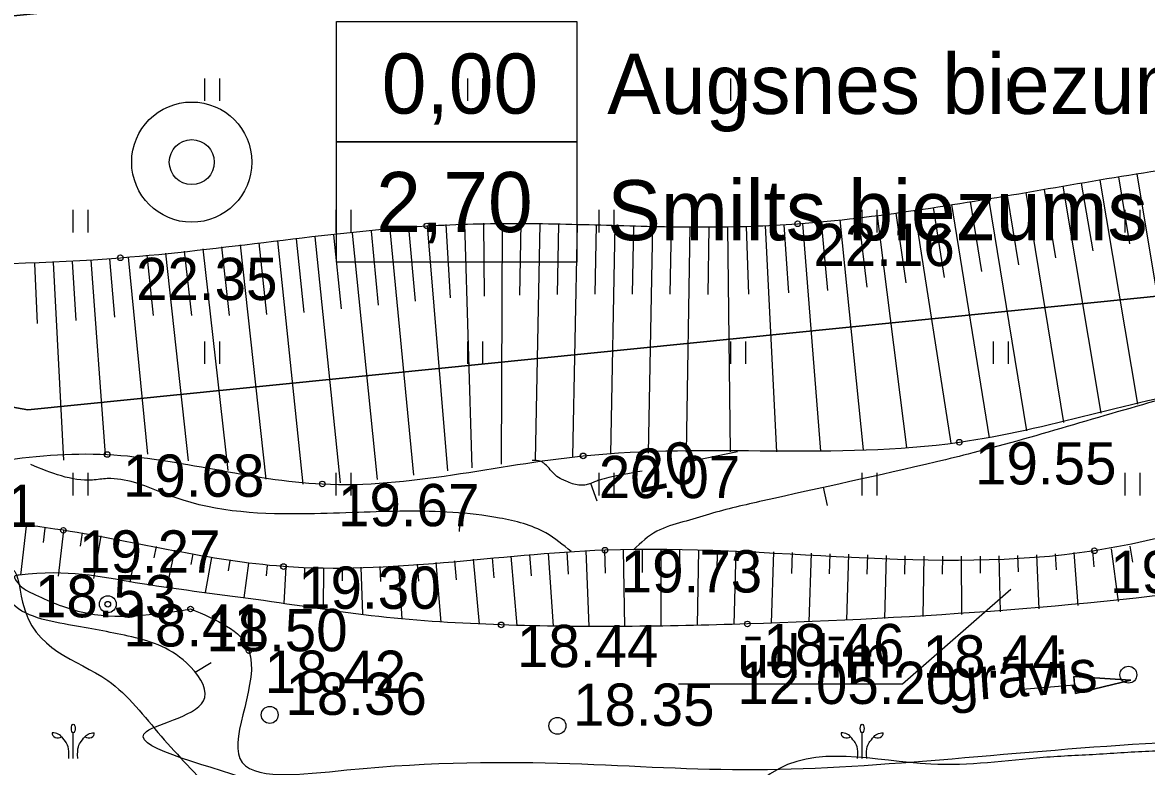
# Model space of a CAD drawing. Extents: x 521824 to 524158, y 294774 to 296228.
# Drawn here: x 522086.65 to 522116.57, y 296008.78 to 296028.59 of the extents above; entities that cross this region are included whole.
import ezdxf

# ---------------------------------------------------------------- set-up
doc = ezdxf.new("R2010")
doc.units = 0
for name, color, linetype in [('GL Urbumi Krajumu aprekina plans', 7, 'Continuous'), ('GL4 Segkartas izplatības laukums', 7, 'Continuous'), ('GL7 Citi Izplatības laukumi', 7, 'Continuous'), ('HIDG_AATZ_####_TKST_#', 7, 'Continuous'), ('HIDG_ELEM_####_####_#', 7, 'Continuous'), ('HIDG_GRAV_####_####_#', 7, 'Continuous'), ('HIDG_GRAV_####_TKST_#', 7, 'Continuous'), ('HIDG_UATZ_####_TKST_#', 7, 'Continuous'), ('RELJ_AATZ_####_TKST_#', 7, 'Continuous'), ('RELJ_ELEM_####_####_#', 7, 'Continuous'), ('RELJ_HORZ_####_TKST_#', 7, 'Continuous'), ('RELJ_HORZ_PAMT_####_#', 7, 'Continuous'), ('RELJ_HORZ_RESN_####_#', 7, 'Continuous'), ('RELJ_NOGA_####_####_#', 7, 'Continuous'), ('RELJ_NOGL_####_####_#', 7, 'Continuous'), ('TERT_ELEM_####_####_#', 7, 'Continuous'), ('TERT_KONT_####_####_#', 7, 'Continuous')]:
    doc.layers.add(name, color=color, linetype=linetype)

msp = doc.modelspace()

# ---------------------------------------------------------------- linework, layer by layer
at = {"layer": 'GL Urbumi Krajumu aprekina plans'}
for points in [[(522095.004, 296028.61), (522101.404, 296028.61), (522101.404, 296025.41), (522095.004, 296025.41)], [(522095.004, 296025.41), (522101.404, 296025.41), (522101.404, 296022.21), (522095.004, 296022.21)]]:
    msp.add_lwpolyline(points, close=True, dxfattribs=at)
for radius in [1.6, 0.6]:
    msp.add_circle((522091.154, 296024.871), radius, dxfattribs=at)
at = {"layer": 'GL4 Segkartas izplatības laukums'}
msp.add_lwpolyline([(522035.409, 296019.72), (522041.36, 296024.307), (522231.747, 296043.148), (522236.101, 296038.183), (522198.651, 296029.427), (522189.713, 296025.592), (522167.466, 296021.53), (522139.559, 296023.596), (522113.856, 296021.004), (522086.791, 296018.275), (522076.123, 296020.164), (522036.859, 296015.29)], close=True, dxfattribs=at)
at = {"layer": 'GL7 Citi Izplatības laukumi'}
msp.add_lwpolyline([(522036.859, 296015.29), (522076.123, 296020.164), (522086.791, 296018.275), (522113.856, 296021.004), (522139.559, 296023.596), (522167.466, 296021.53), (522189.713, 296025.592), (522198.651, 296029.427), (522236.101, 296038.183), (522231.747, 296043.148), (522041.36, 296024.307), (522035.409, 296019.72), (522036.859, 296015.29)], dxfattribs=at)
at = {"layer": 'HIDG_ELEM_####_####_#'}
for p, q in [((522114.675, 296010.731), (522114.637, 296011.18)), ((522114.637, 296011.18), (522116.151, 296011.082)), ((522116.151, 296011.082), (522114.675, 296010.731)), ((522113.161, 296010.829), (522114.656, 296010.956))]:
    msp.add_line(p, q, dxfattribs=at)
msp.add_lwpolyline([(522114.656, 296010.956), (522114.675, 296010.731), (522116.151, 296011.082), (522114.637, 296011.18), (522114.656, 296010.956)], dxfattribs=at)
for centre in [(522088.919, 296013.103), (522116.087, 296011.227), (522093.229, 296010.157), (522100.887, 296009.867)]:
    msp.add_circle(centre, 0.225, dxfattribs=at)
at = {"layer": 'HIDG_GRAV_####_####_#'}
for points in [[(522091.121, 296012.976), (522092.677, 296011.868), (522092.434, 296009), (522095.282, 296008.691), (522106.173, 296008.702), (522116.886, 296009.415), (522127.197, 296009.97), (522145.108, 296014.247), (522158.761, 296014.777), (522175.265, 296015.722), (522181.257, 296017.136), (522181.909, 296017.173), (522183.274, 296011.283)], [(522135.118, 296016.825), (522133.045, 296016.353), (522119.718, 296013.704), (522105.945, 296012.578), (522099.392, 296012.553), (522096.134, 296012.774), (522092.859, 296013.228), (522089.643, 296013.676), (522086.561, 296013.88), (522086.436, 296013.837), (522086.479, 296013.725), (522086.923, 296013.385), (522088.207, 296012.901), (522091.121, 296012.976)]]:
    msp.add_spline(points, degree=3, dxfattribs=at)
at = {"layer": 'HIDG_UATZ_####_TKST_#'}
msp.add_lwpolyline([(522104.107, 296010.988), (522110.073, 296010.988), (522112.956, 296013.503)], dxfattribs=at)
at = {"layer": 'RELJ_ELEM_####_####_#'}
for centre in [(522107.283, 296023.23), (522097.412, 296023.172), (522089.253, 296022.325), (522111.587, 296017.416), (522088.904, 296017.088), (522101.572, 296017.052), (522094.629, 296016.304), (522087.735, 296015.07), (522102.155, 296014.541), (522115.182, 296014.525), (522093.594, 296014.106), (522088.919, 296013.103), (522091.121, 296012.976), (522099.392, 296012.553), (522105.945, 296012.578), (522092.677, 296011.868)]:
    msp.add_circle(centre, 0.075, dxfattribs=at)
at = {"layer": 'RELJ_HORZ_PAMT_####_#'}
for p, q in [((522108.079, 296015.73), (522107.97, 296016.218)), ((522098.278, 296015.041), (522098.309, 296015.54)), ((522091.671, 296011.545), (522091.242, 296011.288))]:
    msp.add_line(p, q, dxfattribs=at)
for points in [[(522117.582, 296018.72), (522117.297, 296018.644), (522111.943, 296017.13), (522110.977, 296016.893), (522106.356, 296015.854), (522104.932, 296015.502), (522104.229, 296015.292), (522103.534, 296015.045), (522102.914, 296014.555)], [(522101.255, 296014.503), (522100.578, 296015), (522099.347, 296015.396), (522098.1, 296015.548), (522095.59, 296015.547), (522094.254, 296015.508), (522090.709, 296015.941), (522089.262, 296016.424), (522088.906, 296016.446), (522088.511, 296016.409), (522086.87, 296016.818)], [(522148.922, 295987.907), (522148.552, 295987.672), (522148.13, 295987.547), (522142.145, 295984.715), (522140.627, 295984.14), (522138.684, 295984.539), (522138.079, 295984.82), (522136.131, 295985.03), (522135.49, 295984.543), (522137.464, 295983.3), (522138.906, 295981.587), (522137.92, 295981.159), (522136.668, 295979.841), (522134.454, 295979.765), (522132.917, 295981.68), (522132.347, 295981.94), (522130.67, 295983.065), (522129.163, 295984.385), (522127.535, 295986.166), (522125.611, 295988.145), (522124.556, 295989.313), (522123.674, 295991.099), (522122.931, 295991.88), (522120.148, 295992.607), (522113.348, 295989.576), (522112.896, 295989.445), (522112.055, 295989.829), (522111.032, 295990.862), (522110.41, 295992.733), (522110.011, 295994.047), (522109.634, 295994.629), (522107.294, 295996.519), (522107.125, 295997.948), (522109.054, 295999.781), (522111.627, 295999.833), (522112.509, 295999.607), (522113.225, 295999.56), (522116.018, 295998.918), (522117.525, 295998.295), (522117.804, 295999.078), (522117.857, 296000.377), (522117.21, 296003.104), (522115.45, 296003.973), (522113.854, 296004.668), (522112.181, 296005.288), (522110.957, 296005.073), (522109.538, 296004.776), (522107.962, 296005.969), (522108.089, 296007.122), (522109.448, 296007.712), (522113.238, 296007.845), (522113.411, 296007.152), (522113.904, 296006.876), (522116.143, 296006.873), (522119.594, 296006.195), (522119.864, 296006.152), (522119.969, 296006.174), (522125.143, 296008.842), (522127.842, 296009.01), (522129.451, 296008.699), (522130.726, 296008.377), (522130.898, 296008.393), (522131.43, 296008.639), (522134.341, 296010.531), (522136.866, 296011.095), (522140.038, 296011.621), (522143.287, 296012.722), (522147.223, 296013.232), (522147.912, 296013.352), (522151.159, 296013.727), (522152.637, 296013.188), (522160.473, 296010.584), (522163.167, 296012.474), (522166.885, 296013.245), (522174.018, 296014.184), (522179.448, 296015.31), (522180.074, 296015.597), (522181.317, 296015.467), (522181.799, 296014.868), (522182.175, 296012.697), (522181.883, 296011.954), (522177.242, 296010.373), (522176.264, 296009.891), (522175.768, 296009.558), (522172.684, 296008.401), (522168.721, 296007.952), (522167.696, 296007.902), (522160.834, 296005.775), (522159.869, 296005.009), (522158.414, 295999.127), (522158.015, 295997.98), (522157.507, 295997.03)], [(522147.001, 296013.879), (522145.334, 296014.111), (522144.908, 296014.079), (522138.003, 296012.088), (522137.814, 296012.008), (522135.146, 296011.271), (522131.635, 296010.287), (522130.341, 296009.639), (522127.864, 296009.75), (522127.714, 296009.761), (522127.564, 296009.8), (522127.264, 296009.832), (522127.105, 296009.79), (522126.615, 296009.677), (522125.425, 296009.552), (522124.235, 296009.457), (522121.853, 296009.334), (522117.084, 296009.201), (522116.821, 296009.194), (522115.322, 296009.109), (522113.823, 296009.021), (522110.825, 296008.845), (522106.552, 296008.587), (522106.42, 296008.498), (522105.24, 296008.381), (522103.71, 296008.042), (522102.575, 296008.01), (522101.436, 296008.101), (522100.295, 296008.227), (522099.156, 296008.295), (522097.506, 296008.302), (522096.685, 296008.185), (522096.274, 296008.062), (522096.069, 296007.981), (522095.864, 296007.884), (522092.757, 296008.408), (522089.948, 296009.718), (522091.502, 296010.619), (522091.012, 296011.544), (522089.457, 296012.256), (522087.875, 296012.556), (522086.266, 296013.266), (522086.078, 296014.194)]]:
    msp.add_spline(points, degree=3, dxfattribs=at)
at = {"layer": 'RELJ_HORZ_RESN_####_#'}
for p, q in [((522105.685, 296017.157), (522104.348, 296016.884)), ((522101.946, 296015.85), (522101.775, 296016.32))]:
    msp.add_line(p, q, dxfattribs=at)
msp.add_spline([(522103.148, 296016.646), (522102.129, 296016.442), (522101.999, 296016.405), (522101.872, 296016.357), (522101.745, 296016.309), (522101.682, 296016.289), (522101.618, 296016.275), (522101.454, 296016.272), (522101.288, 296016.311), (522101.122, 296016.376), (522101.039, 296016.414), (522100.957, 296016.452), (522100.798, 296016.57), (522100.664, 296016.722), (522100.529, 296016.856), (522100.451, 296016.901), (522100.363, 296016.922), (522100.219, 296016.932)], degree=3, dxfattribs=at)
at = {"layer": 'RELJ_NOGA_####_####_#'}
for p, q in [((522115.82, 296024.477), (522116.118, 296022.698)), ((522116.313, 296024.56), (522117.29, 296018.655)), ((522114.341, 296024.229), (522115.353, 296018.186)), ((522114.834, 296024.312), (522115.137, 296022.511)), ((522115.327, 296024.395), (522116.332, 296018.429)), ((522112.367, 296023.903), (522113.371, 296017.721)), ((522112.861, 296023.984), (522113.163, 296022.138)), ((522113.354, 296024.065), (522114.358, 296017.943)), ((522113.847, 296024.146), (522114.15, 296022.321)), ((522110.392, 296023.586), (522111.359, 296017.389)), ((522110.886, 296023.665), (522111.184, 296021.802)), ((522111.38, 296023.744), (522112.38, 296017.533)), ((522111.874, 296023.823), (522112.176, 296021.963)), ((522107.911, 296023.283), (522108.077, 296021.456)), ((522108.409, 296023.331), (522109.027, 296017.213)), ((522108.906, 296023.384), (522109.122, 296021.542)), ((522109.403, 296023.445), (522110.18, 296017.279)), ((522109.898, 296023.512), (522110.159, 296021.656)), ((522095.428, 296022.982), (522096.091, 296016.425)), ((522095.926, 296023.032), (522096.12, 296021.066)), ((522096.423, 296023.081), (522097.056, 296016.536)), ((522096.921, 296023.128), (522097.103, 296021.168)), ((522097.419, 296023.173), (522097.964, 296016.652)), ((522097.918, 296023.209), (522098.034, 296021.255)), ((522098.417, 296023.232), (522098.612, 296016.737)), ((522098.917, 296023.243), (522098.938, 296021.306)), ((522099.417, 296023.245), (522099.388, 296016.835)), ((522099.917, 296023.238), (522099.879, 296021.332)), ((522100.417, 296023.228), (522100.293, 296016.94)), ((522100.917, 296023.218), (522100.878, 296021.349)), ((522101.417, 296023.208), (522101.287, 296017.031)), ((522101.916, 296023.197), (522101.88, 296021.358)), ((522102.416, 296023.187), (522102.303, 296017.093)), ((522102.916, 296023.178), (522102.882, 296021.359)), ((522103.416, 296023.169), (522103.304, 296017.128)), ((522103.916, 296023.16), (522103.884, 296021.354)), ((522104.416, 296023.151), (522104.315, 296017.147)), ((522104.916, 296023.143), (522104.893, 296021.346)), ((522105.416, 296023.143), (522105.488, 296017.155)), ((522105.916, 296023.154), (522105.978, 296021.355)), ((522106.415, 296023.174), (522106.718, 296017.162)), ((522106.915, 296023.204), (522107.037, 296021.393)), ((522107.413, 296023.24), (522107.894, 296017.178)), ((522092.444, 296022.67), (522093.129, 296016.429)), ((522092.941, 296022.725), (522093.146, 296020.812)), ((522093.439, 296022.777), (522094.112, 296016.303)), ((522093.936, 296022.829), (522094.14, 296020.871)), ((522094.433, 296022.88), (522095.108, 296016.336)), ((522094.931, 296022.932), (522095.133, 296020.966)), ((522089.959, 296022.396), (522090.126, 296020.786)), ((522090.457, 296022.449), (522091.061, 296016.921)), ((522090.954, 296022.504), (522091.145, 296020.791)), ((522091.451, 296022.559), (522092.112, 296016.663)), ((522091.947, 296022.615), (522092.152, 296020.791)), ((522086.968, 296022.172), (522087.035, 296020.578)), ((522087.468, 296022.195), (522087.74, 296016.934)), ((522087.967, 296022.224), (522088.069, 296020.659)), ((522088.466, 296022.258), (522088.845, 296017.08)), ((522088.964, 296022.299), (522089.1, 296020.746)), ((522089.462, 296022.345), (522089.972, 296017.101)), ((522086.747, 296015.184), (522086.597, 296013.879)), ((522087.244, 296015.126), (522087.201, 296014.748)), ((522087.741, 296015.069), (522087.595, 296013.847)), ((522088.237, 296015.004), (522088.184, 296014.65)), ((522088.73, 296014.926), (522088.536, 296013.792)), ((522089.222, 296014.837), (522089.161, 296014.511)), ((522089.713, 296014.741), (522089.504, 296013.694)), ((522090.203, 296014.642), (522090.141, 296014.337)), ((522116.125, 296014.648), (522116.198, 296014.225)), ((522090.693, 296014.542), (522090.493, 296013.557)), ((522091.183, 296014.444), (522091.127, 296014.157)), ((522091.675, 296014.351), (522091.507, 296013.416)), ((522098.649, 296014.298), (522098.802, 296012.574)), ((522099.147, 296014.342), (522099.195, 296013.806)), ((522099.646, 296014.385), (522099.804, 296012.54)), ((522100.144, 296014.427), (522100.188, 296013.857)), ((522100.642, 296014.464), (522100.778, 296012.519)), ((522101.141, 296014.496), (522101.176, 296013.901)), ((522101.641, 296014.522), (522101.727, 296012.509)), ((522102.14, 296014.541), (522102.158, 296013.931)), ((522102.64, 296014.552), (522102.673, 296012.51)), ((522103.14, 296014.557), (522103.145, 296013.944)), ((522103.64, 296014.559), (522103.637, 296012.52)), ((522104.14, 296014.556), (522104.135, 296013.948)), ((522104.64, 296014.549), (522104.607, 296012.539)), ((522105.14, 296014.54), (522105.128, 296013.943)), ((522105.64, 296014.527), (522105.587, 296012.566)), ((522106.14, 296014.513), (522106.122, 296013.934)), ((522106.639, 296014.498), (522106.581, 296012.6)), ((522107.139, 296014.481), (522107.12, 296013.922)), ((522107.639, 296014.464), (522107.578, 296012.636)), ((522108.139, 296014.448), (522108.121, 296013.91)), ((522108.638, 296014.432), (522108.584, 296012.677)), ((522109.138, 296014.417), (522109.124, 296013.901)), ((522109.638, 296014.403), (522109.595, 296012.722)), ((522110.138, 296014.392), (522110.128, 296013.899)), ((522110.638, 296014.384), (522110.614, 296012.773)), ((522111.138, 296014.379), (522111.134, 296013.906)), ((522111.638, 296014.378), (522111.641, 296012.833)), ((522112.138, 296014.381), (522112.143, 296013.926)), ((522112.638, 296014.389), (522112.671, 296012.901)), ((522113.137, 296014.402), (522113.152, 296013.963)), ((522113.637, 296014.422), (522113.699, 296012.979)), ((522114.136, 296014.448), (522114.161, 296014.02)), ((522114.635, 296014.481), (522114.74, 296013.069)), ((522115.134, 296014.521), (522115.17, 296014.1)), ((522115.631, 296014.574), (522115.814, 296013.176)), ((522092.168, 296014.268), (522092.124, 296013.991)), ((522092.663, 296014.196), (522092.542, 296013.272)), ((522093.159, 296014.14), (522093.133, 296013.858)), ((522093.658, 296014.102), (522093.603, 296013.125)), ((522094.157, 296014.081), (522094.149, 296013.772)), ((522094.657, 296014.072), (522094.655, 296012.979)), ((522095.157, 296014.075), (522095.162, 296013.725)), ((522095.657, 296014.088), (522095.703, 296012.834)), ((522096.157, 296014.11), (522096.177, 296013.706)), ((522096.656, 296014.138), (522096.749, 296012.701)), ((522097.155, 296014.173), (522097.188, 296013.718)), ((522097.653, 296014.212), (522097.782, 296012.621)), ((522098.151, 296014.254), (522098.195, 296013.756))]:
    msp.add_line(p, q, dxfattribs=at)
for points in [[(522083.469, 296022.122), (522089.253, 296022.325), (522093.331, 296022.766), (522097.412, 296023.172), (522099.877, 296023.239), (522102.348, 296023.189), (522104.819, 296023.145), (522107.283, 296023.23), (522110.427, 296023.591), (522113.558, 296024.098), (522116.686, 296024.621), (522119.823, 296025.032), (522122.353, 296025.216), (522124.893, 296025.318), (522127.433, 296025.416), (522129.962, 296025.585), (522132.417, 296026.013), (522132.758, 296026.1)], [(522133.095, 296021.57), (522129.928, 296019.376), (522121.46, 296016.194), (522115.182, 296014.525), (522102.155, 296014.541), (522093.594, 296014.106), (522087.735, 296015.07), (522084.084, 296015.49)]]:
    msp.add_spline(points, degree=3, dxfattribs=at)
at = {"layer": 'RELJ_NOGL_####_####_#'}
msp.add_spline([(522082.859, 296016.286), (522088.904, 296017.088), (522094.629, 296016.304), (522101.572, 296017.052), (522111.587, 296017.416), (522118.583, 296018.92), (522125.28, 296019.869), (522127.919, 296020.744), (522133.095, 296021.57)], degree=3, dxfattribs=at)
at = {"layer": 'TERT_ELEM_####_####_#'}
for p, q in [((522091.5, 296026.5), (522091.5, 296027.1)), ((522091.9, 296026.5), (522091.9, 296027.1)), ((522098.5, 296026.5), (522098.5, 296027.1)), ((522098.9, 296026.5), (522098.9, 296027.1)), ((522105.5, 296026.5), (522105.5, 296027.1)), ((522105.9, 296026.5), (522105.9, 296027.1)), ((522112.5, 296026.5), (522112.5, 296027.1)), ((522112.9, 296026.5), (522112.9, 296027.1)), ((522088, 296023), (522088, 296023.6)), ((522088.4, 296023), (522088.4, 296023.6)), ((522095, 296023), (522095, 296023.6)), ((522095.4, 296023), (522095.4, 296023.6)), ((522102, 296023), (522102, 296023.6)), ((522102.4, 296023), (522102.4, 296023.6)), ((522109, 296023), (522109, 296023.6)), ((522109.4, 296023), (522109.4, 296023.6)), ((522116, 296023), (522116, 296023.6)), ((522116.4, 296023), (522116.4, 296023.6)), ((522091.5, 296019.5), (522091.5, 296020.1)), ((522091.9, 296019.5), (522091.9, 296020.1)), ((522098.5, 296019.5), (522098.5, 296020.1)), ((522098.9, 296019.5), (522098.9, 296020.1)), ((522105.5, 296019.5), (522105.5, 296020.1)), ((522105.9, 296019.5), (522105.9, 296020.1)), ((522112.5, 296019.5), (522112.5, 296020.1)), ((522112.9, 296019.5), (522112.9, 296020.1)), ((522088, 296016), (522088, 296016.6)), ((522088.4, 296016), (522088.4, 296016.6)), ((522095, 296016), (522095, 296016.6)), ((522095.4, 296016), (522095.4, 296016.6)), ((522102, 296016), (522102, 296016.6)), ((522102.4, 296016), (522102.4, 296016.6)), ((522109, 296016), (522109, 296016.6)), ((522109.4, 296016), (522109.4, 296016.6)), ((522116, 296016), (522116, 296016.6)), ((522116.4, 296016), (522116.4, 296016.6)), ((522088, 296009), (522088, 296009.681)), ((522088, 296009), (522088, 296009.681)), ((522109, 296009), (522109, 296009.681))]:
    msp.add_line(p, q, dxfattribs=at)
for centre in [(522088, 296009.795), (522088, 296009.795), (522109, 296009.795)]:
    msp.add_ellipse(centre, major_axis=(0, 0.114), ratio=0.447069, dxfattribs=at)
for centre, major_axis, start_param, end_param in [((522087.586, 296009.658), (-0.147, 0), 6.117242, 8.627806), ((522087.586, 296009.658), (-0.147, 0), 6.117242, 8.627806), ((522088.414, 296009.658), (0.147, 0), 3.938565, 6.449128), ((522088.414, 296009.658), (0.147, 0), 3.938565, 6.449128), ((522108.586, 296009.658), (-0.147, 0), 6.117242, 8.627806), ((522109.414, 296009.658), (0.147, 0), 3.938565, 6.449128)]:
    msp.add_ellipse(centre, major_axis=major_axis, ratio=0.769466, start_param=start_param, end_param=end_param, dxfattribs=at)
for points in [[(522087.689, 296009.577), (522087.651, 296009.617), (522087.584, 296009.672), (522087.445, 296009.68), (522087.441, 296009.676)], [(522087.689, 296009.577), (522087.651, 296009.617), (522087.584, 296009.672), (522087.445, 296009.68), (522087.441, 296009.676)], [(522087.879, 296009), (522087.902, 296009.288), (522087.786, 296009.465), (522087.696, 296009.568), (522087.689, 296009.577)], [(522087.879, 296009), (522087.902, 296009.288), (522087.786, 296009.465), (522087.696, 296009.568), (522087.689, 296009.577)], [(522088.121, 296009), (522088.098, 296009.288), (522088.214, 296009.465), (522088.304, 296009.568), (522088.311, 296009.577)], [(522088.121, 296009), (522088.098, 296009.288), (522088.214, 296009.465), (522088.304, 296009.568), (522088.311, 296009.577)], [(522088.311, 296009.577), (522088.349, 296009.617), (522088.417, 296009.672), (522088.555, 296009.68), (522088.559, 296009.676)], [(522088.311, 296009.577), (522088.349, 296009.617), (522088.417, 296009.672), (522088.555, 296009.68), (522088.559, 296009.676)], [(522108.689, 296009.577), (522108.651, 296009.617), (522108.584, 296009.672), (522108.445, 296009.68), (522108.441, 296009.676)], [(522108.879, 296009), (522108.902, 296009.288), (522108.786, 296009.465), (522108.696, 296009.568), (522108.689, 296009.577)], [(522109.121, 296009), (522109.098, 296009.288), (522109.214, 296009.465), (522109.304, 296009.568), (522109.311, 296009.577)], [(522109.311, 296009.577), (522109.349, 296009.617), (522109.417, 296009.672), (522109.555, 296009.68), (522109.559, 296009.676)]]:
    msp.add_open_spline(points, degree=3, dxfattribs=at)
at = {"layer": 'TERT_KONT_####_####_#'}
msp.add_spline([(522062.275, 296004.76), (522062.725, 296005.147), (522062.873, 296005.568), (522062.817, 296006.002), (522062.703, 296006.523), (522062.324, 296007.704), (522061.781, 296008.87), (522061.294, 296009.588), (522061.121, 296009.777), (522060.91, 296009.942), (522059.978, 296010.31), (522058.425, 296010.615), (522057.122, 296010.885), (522056.772, 296011.066), (522056.733, 296011.31), (522057.338, 296012.131), (522058.353, 296013.124), (522059.611, 296014.113), (522060.945, 296014.921), (522061.9, 296015.256), (522062.906, 296015.38), (522064.977, 296015.245), (522066.972, 296015.017), (522067.883, 296015.023), (522068.704, 296015.193), (522068.84, 296015.265), (522069.172, 296015.683), (522069.512, 296016.498), (522069.846, 296017.265), (522070.048, 296017.513), (522070.293, 296017.61), (522070.943, 296017.474), (522071.609, 296017.09), (522072.989, 296015.881), (522074.438, 296014.587), (522075.189, 296014.096), (522075.572, 296013.923), (522075.96, 296013.81), (522077.14, 296013.718), (522078.399, 296013.837), (522079.061, 296013.954), (522079.716, 296014.086), (522080.371, 296014.22), (522081.029, 296014.341), (522082.31, 296014.505), (522082.952, 296014.553), (522083.593, 296014.58), (522084.77, 296014.367), (522085.055, 296014.254), (522085.328, 296014.126), (522085.834, 296013.81), (522086.313, 296014.041), (522086.647, 296013.162), (522088.917, 296011.073), (522090.338, 296009.591), (522091.73, 296008.067), (522092.394, 296007.257), (522093.014, 296006.421), (522093.66, 296005.598), (522094.014, 296005.204), (522094.401, 296004.827), (522095.35, 296004.152), (522096.396, 296003.67), (522096.943, 296003.478)], degree=3, dxfattribs=at)

# ---------------------------------------------------------------- texts
at = {"layer": 'GL Urbumi Krajumu aprekina plans'}
for s, p in [('0,00', (522096.21, 296026.162)), ('Augsnes biezums', (522102.215, 296026.154)), ('2,70', (522096.065, 296023.008)), ('Smilts biezums', (522102.215, 296022.79))]:
    msp.add_text(s, height=1.6, dxfattribs=at).set_placement(p)
at = {"layer": 'HIDG_AATZ_####_TKST_#'}
for s, p in [(' 18.36', (522093.229, 296010.157)), (' 18.35', (522100.887, 296009.867))]:
    msp.add_text(s, height=1.125, dxfattribs=at).set_placement(p)
at = {"layer": 'HIDG_GRAV_####_TKST_#'}
msp.add_text('grāvis', height=1.125, rotation=3.9488, dxfattribs=at).set_placement((522111.287, 296010.508))
at = {"layer": 'HIDG_UATZ_####_TKST_#'}
for s, p in [('ūd.līm. 18.44', (522105.678, 296011.151)), ('12.05.20', (522105.678, 296010.448))]:
    msp.add_text(s, height=1.125, dxfattribs=at).set_placement(p)
at = {"layer": 'RELJ_AATZ_####_TKST_#'}
for s, p in [(' 22.16', (522107.283, 296022.105)), (' 22.35', (522089.253, 296021.2)), (' 19.55', (522111.587, 296016.291)), (' 19.68', (522088.904, 296015.963)), (' 20.07', (522101.572, 296015.927)), (' 18.81', (522082.859, 296015.161)), (' 19.67', (522094.629, 296015.179)), (' 19.27', (522087.735, 296013.945)), (' 19.73', (522102.155, 296013.416)), (' 19.19', (522115.182, 296013.4)), (' 19.30', (522093.594, 296012.981)), (' 18.53', (522086.561, 296012.755)), (' 18.41', (522088.919, 296011.978)), (' 18.50', (522091.121, 296011.851)), (' 18.44', (522099.392, 296011.428)), (' 18.46', (522105.945, 296011.453)), (' 18.42', (522092.677, 296010.743))]:
    msp.add_text(s, height=1.125, dxfattribs=at).set_placement(p)
at = {"layer": 'RELJ_HORZ_####_TKST_#'}
msp.add_text('20', height=1.125, rotation=11.2138, dxfattribs=at).set_placement((522103.06, 296016.055))

doc.saveas('drawing.dxf')
